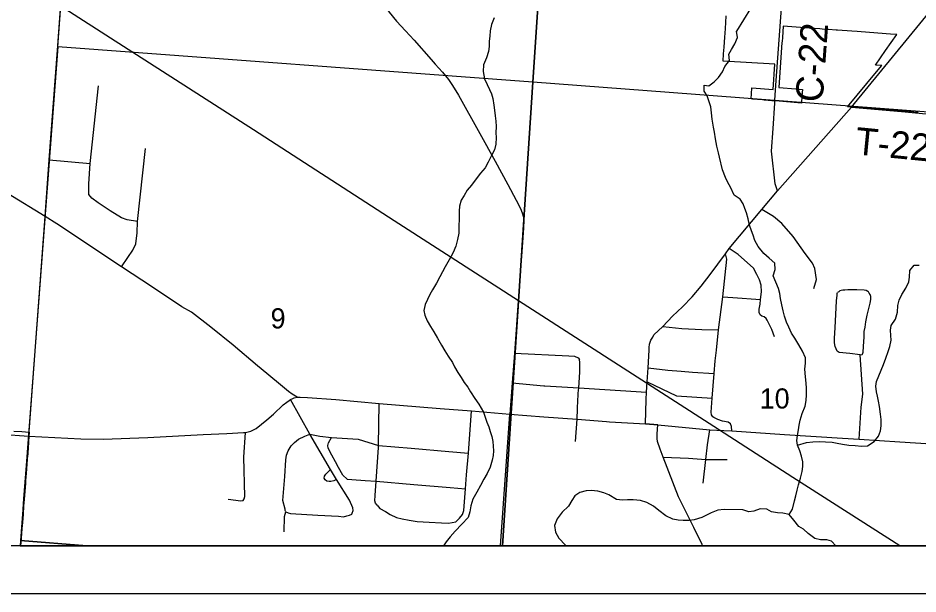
# Model space of a CAD drawing. Extents: x 0 to 34, y 0 to 26.1.
# Drawn here: x 25.464 to 27.339, y 14 to 15.199 of the extents above; entities that cross this region are included whole.
import ezdxf

# ---------------------------------------------------------------- set-up
doc = ezdxf.new("R2010")
doc.units = 0
for name, color, linetype in [('GM_X_City_Street', 7, 'Continuous'), ('GM_X_County_Road', 7, 'Continuous'), ('GM_X_County_Road_Text', 7, 'Continuous'), ('GM_X_Minor_River', 7, 'Continuous'), ('GM_X_Rail_Line', 7, 'Continuous'), ('GM_X_Section', 7, 'Continuous'), ('GM_X_Section_Text', 7, 'Continuous'), ('GM_X_State_Route', 7, 'Continuous'), ('GM_X_Township_Road', 7, 'Continuous'), ('GM_X_Township_Road_Text', 7, 'Continuous'), ('SC_Scratch1', 7, 'Continuous'), ('SH_Data', 7, 'Continuous')]:
    doc.layers.add(name, color=color, linetype=linetype)

msp = doc.modelspace()

# ---------------------------------------------------------------- linework, layer by layer
at = {"layer": 'GM_X_City_Street'}
for p, q in [((25.5288, 14.9037), (25.6139, 14.896)), ((26.8966, 14.2797), (26.941, 14.2799))]:
    msp.add_line(p, q, dxfattribs=at)
for points in [[(25.7129, 14.7752), (25.6912, 14.779), (25.6794, 14.7832), (25.6554, 14.7978), (25.6304, 14.8139), (25.6172, 14.8238), (25.6115, 14.8318), (25.611, 14.8394), (25.6115, 14.8535), (25.6139, 14.896), (25.6315, 15.0581)], [(25.679, 14.6808), (25.6922, 14.7006), (25.703, 14.7157), (25.7091, 14.729), (25.712, 14.7521), (25.7129, 14.7752), (25.729, 14.9273)], [(27.1222, 14.6358), (27.1272, 14.6543), (27.1241, 14.6772), (27.1191, 14.6883), (27.1037, 14.7088), (27.0789, 14.744), (27.0554, 14.7712), (27.0381, 14.786), (27.0134, 14.8003)], [(26.9166, 14.4852), (26.9189, 14.5075), (26.9234, 14.5499), (26.9325, 14.6186), (26.9406, 14.6973), (26.9382, 14.7081)], [(27.2357, 14.6293), (27.2346, 14.6297), (27.2308, 14.632), (27.2266, 14.6323), (27.2118, 14.6328), (27.1928, 14.6328), (27.1867, 14.6325), (27.1821, 14.6321), (27.1791, 14.6317), (27.1764, 14.631), (27.1738, 14.6291), (27.1711, 14.6276)], [(27.2164, 14.322), (27.2206, 14.389), (27.2243, 14.416), (27.2186, 14.4976), (27.2224, 14.4988), (27.2236, 14.4995), (27.2247, 14.5037), (27.2251, 14.5151), (27.2263, 14.5253), (27.2267, 14.5344), (27.2271, 14.5466), (27.2287, 14.5557), (27.2302, 14.5663), (27.2333, 14.5803), (27.236, 14.5917), (27.2394, 14.6054), (27.2406, 14.6129), (27.2406, 14.6194), (27.2391, 14.6232), (27.2372, 14.6262), (27.2357, 14.6293)], [(27.2186, 14.4976), (27.1966, 14.5004), (27.175, 14.5027), (27.1704, 14.5057), (27.1666, 14.5149), (27.1648, 14.5225), (27.1648, 14.5323), (27.1667, 14.5543), (27.1695, 14.6101), (27.1703, 14.6219), (27.1707, 14.6253), (27.1711, 14.6276)], [(26.8074, 14.5565), (26.847, 14.5525), (26.8884, 14.5508), (26.9234, 14.5499)], [(26.4979, 14.5013), (26.6111, 14.4958), (26.6233, 14.4953), (26.6308, 14.4918), (26.6338, 14.4881)], [(26.6312, 14.418), (26.6319, 14.4293), (26.634, 14.4619), (26.6344, 14.4816), (26.6338, 14.4881)], [(26.9137, 14.3674), (26.9114, 14.3691), (26.9089, 14.3729), (26.9082, 14.3782), (26.91, 14.4073), (26.9139, 14.4591), (26.9166, 14.4852)], [(26.7765, 14.4709), (26.8177, 14.466), (26.8453, 14.4636)], [(26.8453, 14.4636), (26.869, 14.4616), (26.9139, 14.4591)], [(26.7748, 14.4416), (26.836, 14.4128), (26.91, 14.4073)], [(26.4935, 14.4394), (26.5594, 14.4333), (26.5613, 14.4332)], [(26.5613, 14.4332), (26.6319, 14.4293), (26.7732, 14.4199)], [(26.1599, 14.1685), (26.1618, 14.1741), (26.1615, 14.1795), (26.1543, 14.1955), (26.1275, 14.2381), (26.115, 14.2591), (26.0715, 14.3327), (26.0316, 14.4045)], [(26.6293, 14.3877), (26.631, 14.415), (26.6311, 14.417), (26.6312, 14.418)], [(26.2117, 14.1846), (26.2083, 14.1892), (26.2075, 14.1937), (26.208, 14.2051), (26.2096, 14.2348), (26.2146, 14.3051), (26.2149, 14.3092), (26.2163, 14.3962)], [(26.6253, 14.3174), (26.6285, 14.364), (26.6292, 14.3857), (26.6293, 14.3877)], [(26.2117, 14.1846), (26.2177, 14.1781), (26.2291, 14.172), (26.239, 14.1655), (26.2526, 14.1593), (26.264, 14.1562), (26.2785, 14.1535), (26.2956, 14.1512), (26.3203, 14.1492), (26.3458, 14.1483), (26.3606, 14.1475), (26.3762, 14.1505), (26.3838, 14.1576), (26.3896, 14.1652), (26.3923, 14.1736), (26.3931, 14.1831), (26.3963, 14.2188), (26.3979, 14.2477), (26.402, 14.2933), (26.4089, 14.3813)], [(26.9509, 14.3393), (26.9503, 14.3486), (26.9484, 14.3539), (26.9433, 14.3575), (26.9317, 14.36), (26.922, 14.3629), (26.916, 14.3657), (26.9137, 14.3674)], [(25.9014, 14.1976), (25.928, 14.1941), (25.933, 14.1948), (25.9349, 14.1979), (25.936, 14.2028), (25.9341, 14.2847), (25.9374, 14.3362)], [(26.0182, 14.1291), (26.0191, 14.1614), (26.0218, 14.1709), (26.0203, 14.1736), (26.02, 14.1766), (26.0157, 14.1945), (26.0193, 14.2444), (26.0214, 14.2792), (26.023, 14.2891), (26.0266, 14.2982), (26.0328, 14.3083), (26.0396, 14.3156), (26.0481, 14.3221), (26.0611, 14.3286), (26.0715, 14.3327), (26.0926, 14.3286), (26.1167, 14.326), (26.1726, 14.3224), (26.2149, 14.3092), (26.2826, 14.3032), (26.3613, 14.2968), (26.402, 14.2933)], [(26.8911, 14.2308), (26.8966, 14.2797), (26.9003, 14.3104), (26.9055, 14.342)], [(26.1496, 14.2392), (26.1405, 14.2472), (26.1314, 14.2632), (26.125, 14.275), (26.1175, 14.2891), (26.1102, 14.3036), (26.1095, 14.3094), (26.1108, 14.3146), (26.1167, 14.326)], [(26.8079, 14.2845), (26.8611, 14.2825), (26.8966, 14.2797)], [(26.1275, 14.2381), (26.1218, 14.2355), (26.1157, 14.2344), (26.1119, 14.234), (26.1069, 14.2348), (26.1039, 14.2379), (26.1013, 14.2413), (26.1024, 14.2455), (26.1051, 14.2492), (26.1093, 14.2534), (26.115, 14.2591)], [(26.1496, 14.2392), (26.1591, 14.238), (26.1868, 14.236), (26.2096, 14.2348), (26.2883, 14.228), (26.3644, 14.2216), (26.3963, 14.2188)], [(26.0218, 14.1709), (26.0264, 14.1686), (26.0313, 14.1678), (26.0887, 14.1642), (26.1313, 14.1617), (26.142, 14.1609), (26.1488, 14.1628), (26.1542, 14.1639), (26.1591, 14.1662), (26.1599, 14.1685)]]:
    msp.add_lwpolyline(points, dxfattribs=at)
at = {"layer": 'GM_X_County_Road'}
for p, q in [((26.7711, 14.3541), (26.7727, 14.4047)), ((26.4687, 14.1), (26.4884, 14.3743)), ((26.7972, 14.3519), (26.7711, 14.3541))]:
    msp.add_line(p, q, dxfattribs=at)
for points in [[(27.2002, 15.0134), (27.3778, 15.2289), (27.3819, 15.2336), (27.3907, 15.2442), (27.512, 15.3902), (27.5127, 15.3911), (27.5248, 15.4055), (27.557, 15.4437), (27.5634, 15.4514), (27.5696, 15.4591), (27.7165, 15.6388), (27.7543, 15.6858)], [(27.0409, 15.0278), (27.0437, 15.0687), (27.0546, 15.2196), (27.0598, 15.2857), (27.0696, 15.4272)], [(27.0462, 14.8393), (27.0413, 14.854), (27.034, 14.9216), (27.0372, 14.9689), (27.0405, 15.0218), (27.0409, 15.0278)], [(26.7727, 14.4047), (26.7732, 14.4199), (26.7748, 14.4416), (26.7765, 14.4709), (26.7787, 14.5076), (26.7786, 14.5133), (26.7794, 14.5197), (26.7814, 14.5262), (26.7826, 14.5285), (26.7864, 14.5349), (26.7887, 14.5395), (26.8074, 14.5565), (26.8273, 14.5781), (26.8483, 14.5974), (26.8682, 14.6186), (26.8873, 14.6409), (26.9061, 14.6652), (26.9382, 14.7081), (26.9457, 14.7193), (27.0134, 14.8003), (27.0462, 14.8393), (27.2002, 15.0134)], [(25.4863, 14.3285), (25.5948, 14.3231), (25.6412, 14.322), (25.7345, 14.3254), (25.8493, 14.3317), (25.899, 14.3341), (25.9332, 14.336), (25.9374, 14.3362), (25.9487, 14.3388), (25.9599, 14.3445), (25.9818, 14.3622), (25.9958, 14.3745), (26.0162, 14.3935), (26.0235, 14.3991), (26.0285, 14.4026), (26.0316, 14.4045), (26.0366, 14.4072), (26.0394, 14.4083), (26.0452, 14.4097)], [(26.0452, 14.4097), (26.0482, 14.41), (26.0513, 14.41), (26.0667, 14.4092), (26.1259, 14.4046), (26.2163, 14.3962), (26.3436, 14.3864), (26.4089, 14.3813), (26.4884, 14.3743)], [(24.4753, 14.3929), (24.4981, 14.391), (24.5942, 14.3831), (24.681, 14.3757), (24.7801, 14.3668), (24.8359, 14.3619), (24.901, 14.356), (24.9197, 14.3551), (24.9415, 14.3549), (24.9819, 14.3557), (25.0005, 14.3558), (25.0503, 14.3545), (25.1341, 14.3521), (25.1593, 14.351), (25.2149, 14.3487), (25.2397, 14.3475), (25.3171, 14.3416), (25.3699, 14.3371), (25.4863, 14.3285)], [(26.8018, 14.3018), (26.7963, 14.3171), (26.7953, 14.3237), (26.7953, 14.3331), (26.7972, 14.3519)], [(26.8653, 14.1511), (26.8396, 14.2022), (26.8079, 14.2845), (26.8018, 14.3018)], [(26.8902, 14.1), (26.8891, 14.1031), (26.8718, 14.1384), (26.8653, 14.1511)]]:
    msp.add_lwpolyline(points, dxfattribs=at)
at = {"layer": 'GM_X_Minor_River'}
for points in [[(26.9903, 15.2185), (26.9606, 15.1719)], [(26.4557, 15.199), (26.4503, 15.1857), (26.4478, 15.1725), (26.4465, 15.1615), (26.4456, 15.1505), (26.4451, 15.1395), (26.4438, 15.1293), (26.4398, 15.1161), (26.4335, 15.1017), (26.433, 15.0873), (26.4354, 15.0721), (26.4409, 15.0603), (26.4461, 15.0503), (26.4501, 15.0408), (26.453, 15.0312), (26.455, 15.0172), (26.4564, 15.0069), (26.4581, 14.9951), (26.4595, 14.9841), (26.4601, 14.9731), (26.4595, 14.9598), (26.4598, 14.9503), (26.4592, 14.9363), (26.4568, 14.9249), (26.4498, 14.9114), (26.4431, 14.8989), (26.4369, 14.8869), (26.4273, 14.876), (26.4165, 14.8613), (26.4088, 14.8508), (26.3999, 14.8403), (26.3933, 14.8298), (26.3872, 14.82), (26.3839, 14.8075), (26.3827, 14.7969), (26.3829, 14.7855), (26.3825, 14.7609), (26.382, 14.751), (26.3795, 14.7377), (26.3756, 14.7238), (26.3701, 14.7109), (26.3623, 14.6955), (26.3534, 14.6808), (26.3483, 14.6706), (26.3425, 14.6601), (26.3359, 14.6469), (26.3273, 14.633), (26.3219, 14.6232), (26.3168, 14.613), (26.3122, 14.6024), (26.3093, 14.5899), (26.3115, 14.5804), (26.3162, 14.5686), (26.3232, 14.5571), (26.3299, 14.5456), (26.338, 14.5326), (26.3461, 14.5177)], [(26.9686, 14.8217), (26.9561, 14.8304), (26.948, 14.8468), (26.9425, 14.8564), (26.9381, 14.8667), (26.9315, 14.8831), (26.9254, 14.909), (26.9233, 14.9185), (26.9201, 14.9322), (26.9169, 14.9474), (26.9148, 14.9611), (26.9127, 14.9714), (26.9099, 14.9881), (26.9086, 15.0018), (26.9072, 15.014), (26.904, 15.0246), (26.8996, 15.0372), (26.8937, 15.0468), (26.8935, 15.059), (26.9033, 15.0581), (26.914, 15.0663), (26.9236, 15.0749), (26.9317, 15.0869), (26.9368, 15.0982), (26.9464, 15.1102), (26.9451, 15.1235), (26.9502, 15.1337), (26.9575, 15.145), (26.963, 15.1582), (26.9606, 15.1719)], [(27.0702, 14.1652), (27.0776, 14.1769), (27.0815, 14.1936), (27.0843, 14.2046), (27.0871, 14.2163), (27.0898, 14.2273), (27.0938, 14.2413), (27.0973, 14.2553), (27.099, 14.2651), (27.0991, 14.2754), (27.0965, 14.2872), (27.0925, 14.2982), (27.0881, 14.31), (27.0867, 14.3195), (27.0879, 14.3298), (27.0903, 14.3415), (27.0912, 14.3517), (27.0932, 14.362), (27.0979, 14.3756), (27.1041, 14.3907), (27.1057, 14.4028), (27.1063, 14.4146), (27.1064, 14.4286), (27.1061, 14.4389), (27.1048, 14.4522), (27.1034, 14.4681), (27.1047, 14.4803), (27.1048, 14.4916), (27.0985, 14.5054), (27.0907, 14.5187), (27.0821, 14.5325), (27.0754, 14.5432), (27.0695, 14.5554), (27.0651, 14.5657), (27.061, 14.5786), (27.0581, 14.5893), (27.0552, 14.6022), (27.0527, 14.6151), (27.0509, 14.6258), (27.0484, 14.6361), (27.0425, 14.649), (27.0373, 14.6624), (27.0413, 14.6756), (27.0406, 14.6885), (27.0286, 14.6993), (27.0174, 14.7085), (27.0058, 14.723), (26.9991, 14.736), (26.9954, 14.7467), (26.9917, 14.7562), (26.9877, 14.7676), (26.9848, 14.7809), (26.9815, 14.7931), (26.9778, 14.8026), (26.9745, 14.8122), (26.9686, 14.8217)], [(27.0881, 14.31), (27.1063, 14.3151), (27.12, 14.3165), (27.134, 14.3171), (27.1465, 14.317), (27.1601, 14.3157), (27.1707, 14.3141), (27.1817, 14.3121), (27.1949, 14.31), (27.2081, 14.3088), (27.221, 14.3079), (27.2339, 14.3085), (27.2476, 14.3175), (27.2565, 14.3288), (27.2608, 14.3397), (27.2624, 14.3503), (27.2625, 14.3629), (27.2611, 14.3746), (27.259, 14.3902), (27.2569, 14.4012), (27.2543, 14.4115), (27.2522, 14.421), (27.2508, 14.4324), (27.2528, 14.4423), (27.2571, 14.454), (27.2672, 14.4774), (27.2722, 14.4907), (27.2769, 14.5046), (27.2804, 14.5149), (27.2829, 14.5281), (27.2826, 14.538), (27.2816, 14.549), (27.2828, 14.5592), (27.2921, 14.5724), (27.296, 14.5868), (27.2969, 14.6005), (27.2997, 14.6114), (27.3051, 14.6235), (27.3136, 14.6363), (27.3198, 14.6496), (27.3214, 14.6594), (27.3223, 14.6734), (27.3311, 14.6847), (27.3414, 14.6846)], [(26.3461, 14.5177), (26.3528, 14.5062), (26.3598, 14.4951), (26.3687, 14.4821), (26.3735, 14.4725), (26.3801, 14.4611), (26.3872, 14.4507), (26.3931, 14.4404), (26.4009, 14.4304), (26.4068, 14.4208), (26.4157, 14.4067), (26.4239, 14.3948), (26.4335, 14.3784), (26.4404, 14.3578), (26.4444, 14.3482), (26.4473, 14.3383), (26.4509, 14.3276), (26.453, 14.3174), (26.454, 14.3079), (26.4543, 14.298), (26.4534, 14.2885), (26.4517, 14.2783), (26.4477, 14.2643), (26.4415, 14.2511), (26.4345, 14.2387), (26.4271, 14.2259), (26.4194, 14.2119), (26.4116, 14.1972), (26.4072, 14.1833), (26.4048, 14.1712), (26.4016, 14.1591), (26.3881, 14.1452), (26.3743, 14.1306), (26.3639, 14.1193), (26.3558, 14.1088), (26.3499, 14.1)], [(26.9737, 14.1753), (26.9354, 14.176), (26.9222, 14.1743), (26.9081, 14.1691), (26.8982, 14.1644), (26.8883, 14.1592), (26.8727, 14.1545), (26.8624, 14.1531), (26.8496, 14.1529), (26.839, 14.1534), (26.828, 14.1554), (26.8137, 14.1625), (26.7988, 14.1741), (26.7875, 14.183), (26.774, 14.1904), (26.7605, 14.1943), (26.7454, 14.1961), (26.7336, 14.1958), (26.7234, 14.1952), (26.7105, 14.1969), (26.6948, 14.2062), (26.6843, 14.2109), (26.6718, 14.2138), (26.6578, 14.2155), (26.6476, 14.2145), (26.6343, 14.2113), (26.624, 14.2042), (26.6174, 14.1944), (26.6104, 14.1827), (26.5978, 14.1704), (26.587, 14.1565), (26.5815, 14.1425), (26.5839, 14.1285), (26.5909, 14.1162), (26.6047, 14.1016), (26.606, 14.1)], [(27.1681, 14.1), (27.1587, 14.1097), (27.1488, 14.1124), (27.136, 14.1126), (27.1242, 14.1157), (27.1103, 14.1261), (27.1006, 14.1346), (27.0908, 14.1407), (27.0803, 14.1537), (27.0702, 14.1652), (27.0574, 14.1684), (27.0464, 14.1689), (27.0339, 14.1709), (27.0238, 14.1767), (27.0098, 14.1772), (26.9968, 14.1725), (26.9866, 14.171), (26.9737, 14.1753)]]:
    msp.add_lwpolyline(points, dxfattribs=at)
at = {"layer": 'GM_X_Rail_Line'}
msp.add_lwpolyline([(27.301, 14.1), (27.0785, 14.2427), (26.9137, 14.3485), (26.2475, 14.7771), (25.9542, 14.966), (25.6567, 15.1572), (25.4759, 15.2734), (25.3538, 15.3521), (25.2892, 15.3938), (25.2593, 15.4116), (25.1825, 15.4531), (24.7379, 15.6913), (24.5774, 15.7768)], dxfattribs=at)
at = {"layer": 'GM_X_Section'}
for points in [[(25.6194, 16.135), (26.1174, 16.097), (26.603, 16.0634), (26.5367, 15.0651), (25.5463, 15.1393)], [(26.603, 16.0634), (26.6185, 16.0611), (27.1167, 16.0245), (27.6154, 15.9857), (27.5444, 14.9891), (26.5367, 15.0651)], [(25.6067, 14.1), (26.4732, 14.1), (26.5367, 15.0651), (25.5463, 15.1393), (25.4688, 14.1111)], [(26.4732, 14.1), (27.4819, 14.1), (27.5444, 14.9891), (26.5367, 15.0651)], [(25.468, 14.1), (25.6067, 14.1), (25.4688, 14.1111)]]:
    msp.add_lwpolyline(points, close=True, dxfattribs=at)
at = {"layer": 'GM_X_State_Route'}
msp.add_line((26.7711, 14.3541), (26.7972, 14.3519), dxfattribs=at)
for points in [[(25.9648, 15.5623), (25.981, 15.5477), (26.0211, 15.5118), (26.0465, 15.4884), (26.0704, 15.4662), (26.0902, 15.4448), (26.1031, 15.4296), (26.1124, 15.4174), (26.1293, 15.3918), (26.1523, 15.3544), (26.1867, 15.2931), (26.2066, 15.2594), (26.2208, 15.235), (26.2372, 15.2112), (26.2524, 15.1924), (26.2713, 15.1725), (26.2888, 15.1526), (26.3243, 15.1127), (26.3329, 15.1032), (26.3484, 15.0861), (26.3606, 15.0709), (26.3677, 15.0606)], [(26.3677, 15.0606), (26.3693, 15.0582), (26.3813, 15.0386), (26.4261, 14.9586), (26.4576, 14.901), (26.484, 14.8522), (26.5017, 14.8201), (26.5108, 14.8024), (26.514, 14.7937), (26.5161, 14.7865), (26.5174, 14.7779), (26.5172, 14.7622), (26.5142, 14.7221), (26.506, 14.6097), (26.5053, 14.6008)], [(26.5053, 14.6008), (26.5024, 14.5603), (26.4979, 14.5013), (26.4935, 14.4394), (26.4884, 14.3743)], [(26.4884, 14.3743), (26.5594, 14.3687), (26.6285, 14.364), (26.6901, 14.3592)], [(26.6901, 14.3592), (26.6961, 14.3587), (26.7711, 14.3541)], [(26.7972, 14.3519), (26.9055, 14.342), (26.9345, 14.3403)], [(26.9345, 14.3403), (26.9509, 14.3393), (27.0608, 14.3321)], [(27.0608, 14.3321), (27.1814, 14.3243), (27.2164, 14.322), (27.3013, 14.3167), (27.3664, 14.3127), (27.4416, 14.3069), (27.4588, 14.3048), (27.478, 14.3015), (27.4936, 14.2981), (27.5131, 14.293), (27.535, 14.2856), (27.56, 14.2759), (27.5902, 14.2614), (27.6115, 14.2492), (27.6391, 14.2323), (27.6565, 14.2195), (27.6738, 14.2053), (27.706, 14.1756), (27.7598, 14.1208), (27.7803, 14.1)]]:
    msp.add_lwpolyline(points, dxfattribs=at)
at = {"layer": 'GM_X_Township_Road'}
for points in [[(25.4863, 14.3285), (25.5202, 14.7858), (25.5288, 14.9037), (25.5459, 15.1318), (25.5761, 15.543)], [(27.2002, 15.0134), (27.3122, 15.0037), (27.3994, 14.9952), (27.6991, 14.9704), (27.703, 14.9701)], [(25.5202, 14.7858), (25.4431, 14.8332), (25.3898, 14.8663), (25.3549, 14.8818), (25.2995, 14.902)], [(26.0452, 14.4097), (26.0349, 14.4158), (26.0271, 14.4214), (26.0148, 14.432), (25.9822, 14.4588), (25.9629, 14.4749), (25.9123, 14.5178), (25.8655, 14.5552), (25.825, 14.5864), (25.8049, 14.5978), (25.7441, 14.6384), (25.679, 14.6808), (25.5445, 14.7705), (25.5202, 14.7858)], [(27.04, 14.5351), (27.0341, 14.5508), (27.025, 14.5698), (27.0224, 14.5737), (27.0181, 14.5766), (27.0134, 14.5781), (27.0103, 14.5809), (27.0082, 14.5862), (27.0081, 14.5929), (27.01, 14.6033), (27.0107, 14.6127), (27.0129, 14.6292), (27.0119, 14.6426), (27.0086, 14.6539), (27.0032, 14.6649), (26.996, 14.678), (26.9642, 14.7067), (26.9457, 14.7193)], [(26.9325, 14.6186), (26.9528, 14.6174), (27.0107, 14.6127)], [(25.4689, 14.1), (25.4724, 14.1434), (25.476, 14.1978), (25.4863, 14.3285)]]:
    msp.add_lwpolyline(points, dxfattribs=at)
at = {"layer": 'SC_Scratch1'}
for points in [[(27.3394, 15.0026), (27.33, 15.0033), (27.3289, 15.0034), (27.2861, 15.0068), (27.2559, 15.0092), (27.2173, 15.0123), (27.2055, 15.0133), (27.2045, 15.0134), (27.1988, 15.0138), (27.1976, 15.0139), (27.1918, 15.0144), (27.2525, 15.0868), (27.2635, 15.1), (27.2502, 15.101), (27.2716, 15.1314), (27.295, 15.1647), (27.2818, 15.1656), (27.2207, 15.1701), (27.2125, 15.1707), (27.2012, 15.1715), (27.1713, 15.1736), (27.1688, 15.1737), (27.1525, 15.1749), (27.148, 15.1752), (27.1395, 15.1758), (27.1345, 15.1761), (27.1125, 15.1778), (27.0579, 15.1819), (27.0563, 15.1584), (27.0557, 15.1504), (27.0556, 15.1493), (27.0555, 15.1477), (27.0533, 15.1166), (27.0511, 15.0853), (27.0489, 15.0541), (27.0844, 15.0514), (27.0981, 15.0503), (27.0972, 15.0371), (27.0961, 15.022), (27.0497, 15.0257), (27.0412, 15.0263), (27.0345, 15.0269), (27.0187, 15.0282), (27.0153, 15.0285), (26.994, 15.0303), (26.9912, 15.0305), (26.9928, 15.0531), (26.9929, 15.0538), (27.0372, 15.0504), (27.041, 15.1029), (26.9328, 15.1093), (26.9339, 15.1244), (26.9349, 15.1386), (26.9364, 15.1594), (26.9369, 15.1673), (26.9376, 15.1769), (26.9385, 15.1895), (26.9395, 15.2036)], [(25.4552, 14.3392), (25.4719, 14.3379), (25.487, 14.3365), (25.4869, 14.3349), (25.4864, 14.3292), (25.4845, 14.3033), (25.4831, 14.2845), (25.483, 14.2841), (25.4828, 14.2809), (25.4812, 14.2605), (25.4799, 14.2431), (25.4795, 14.2369), (25.479, 14.2302), (25.4777, 14.2133), (25.4764, 14.1964), (25.4759, 14.1897), (25.4754, 14.1834), (25.4741, 14.1664), (25.4728, 14.1487), (25.4723, 14.1428), (25.4718, 14.1356), (25.4703, 14.1164), (25.4691, 14.1), (27.7436, 14.1)]]:
    msp.add_lwpolyline(points, dxfattribs=at)
at = {"layer": 'SH_Data'}
for points in [[(23.4167, 21), (30.4167, 21), (30.4167, 14), (23.4167, 14)], [(23.5167, 20.9), (30.3167, 20.9), (30.3167, 14.1), (23.5167, 14.1)]]:
    msp.add_lwpolyline(points, close=True, dxfattribs=at)

# ---------------------------------------------------------------- texts
at = {"layer": 'GM_X_County_Road_Text'}
msp.add_text('C-22', height=0.05682, rotation=85.8896, dxfattribs=at).set_placement((27.1401, 15.0223))
at = {"layer": 'GM_X_Section_Text'}
for s, height, p in [('9', 0.0419, (25.99, 14.5528)), ('10', 0.04186, (27.0092, 14.3861))]:
    msp.add_text(s, height=height, rotation=0, dxfattribs=at).set_placement(p)
at = {"layer": 'GM_X_Township_Road_Text'}
msp.add_text('T-226', height=0.05682, rotation=354.4014, dxfattribs=at).set_placement((27.2065, 14.9154))

doc.saveas('drawing.dxf')
